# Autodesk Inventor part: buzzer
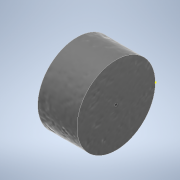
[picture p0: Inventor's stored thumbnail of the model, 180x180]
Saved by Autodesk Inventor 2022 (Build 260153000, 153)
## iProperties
Created: 2021-06
Part Number: buzzer
Material: Generic
Document SubType Name: Modeling
Designer: Delll
Density: 1 g/cm^3
Appearance: Fine Textured - Black
Author: Delll
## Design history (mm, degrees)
sketch "Sketch1"
  geometry: 1 further point
sketch "Sketch2"
  geometry: L1 (0, 0)-(0, 15); L2 (0, 15)-(15, 15); L3 (15, 15)-(15, 0); L4 (15, 0)-(0, 0)
  constraints: 8 end point, 3 perpendicular, 1 vertical
  dimensions: "d0" = 15 distance of L1.start L1.end; "d1" = 15 distance of L1.end L2.end
revolve "Revolution1" sketch "Sketch2" stored, may be unused: angle "d2" = 360 deg
sketch "Sketch3"
  geometry: 2 further points
hole "Hole1" sketch "Sketch3" at (-0.007, -0.028) diameter "d3" = 1; stored, may be unused: countersink angle "d7" = 90 deg, drill point angle "d9" = 0 deg; dims "d4" = 6, "d5" = 19.05, "d6" = 4.775, "d8" = 1
sketch "Sketch4"
  geometry: 2 further points
hole "Hole2" sketch "Sketch4" at (-0.03, 0.037) diameter "d10" = 1; stored, may be unused: countersink angle "d14" = 90 deg, drill point angle "d16" = 0 deg; dims "d11" = 6, "d12" = 4, "d13" = 2, "d15" = 1
sketch "Sketch6"
  geometry: 1 further point
sketch "Sketch7"
  geometry: C1 r 0.811 at (0.04, -6.478); C2 r 0.898 at (0.04, 7.953); 1 further point
  constraints: 2 centre point
extrude "Extrusion2" join sketch "Sketch7" distance "d21" = 5; taper "d22" = 0 deg
body "Solid1"
